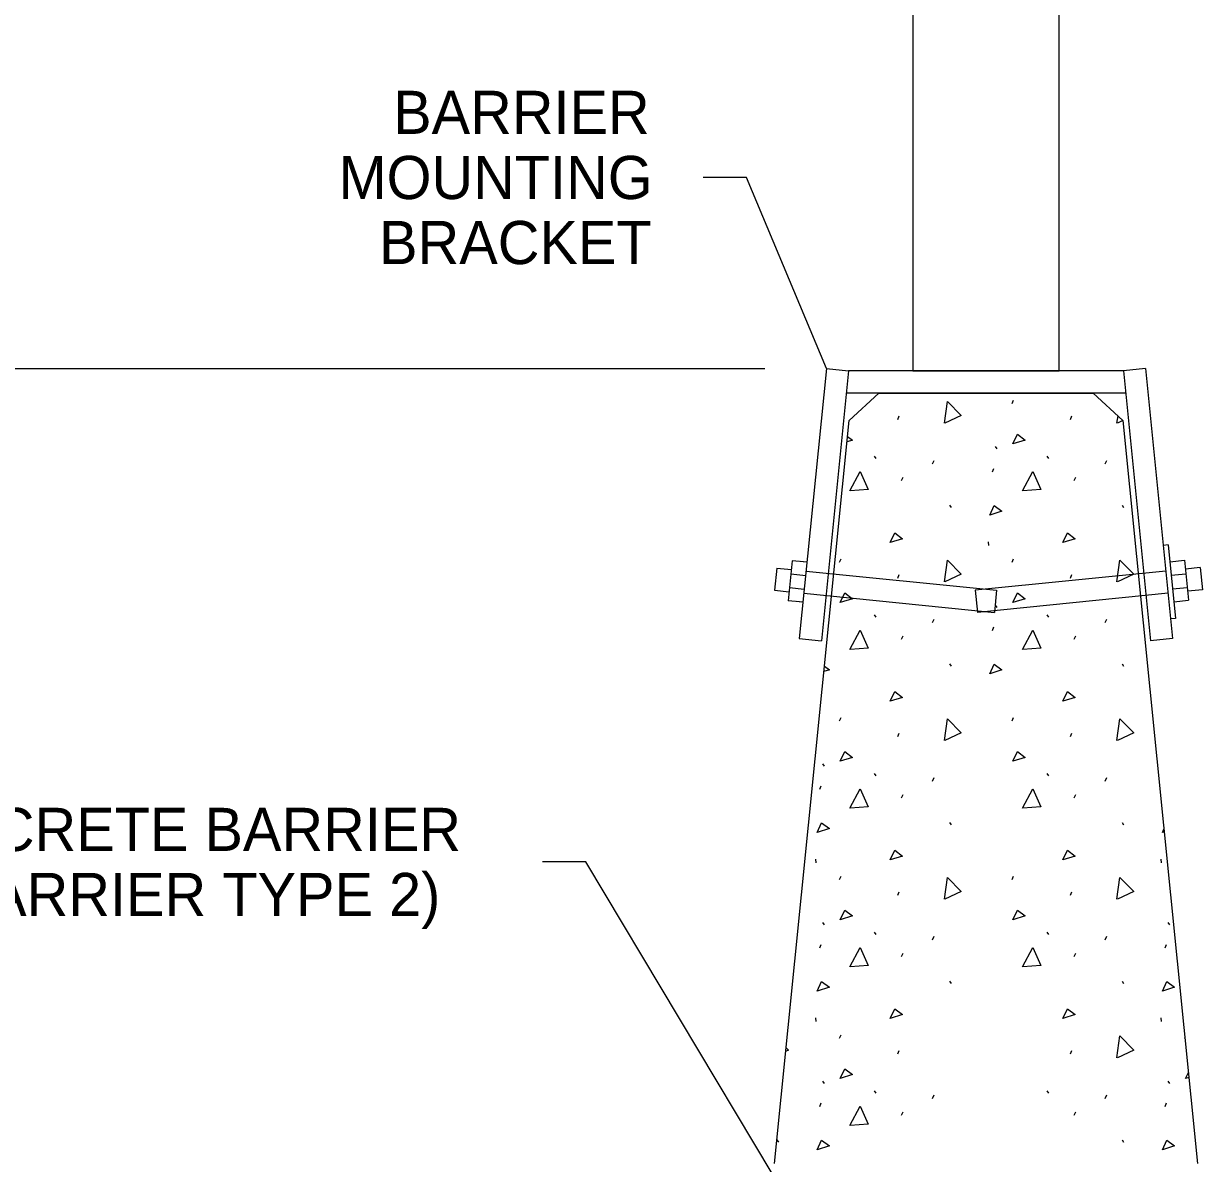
# Model space of a CAD drawing. Extents: x 99988 to 100172, y 99995 to 100047.
# Drawn here: x 100000.814 to 100002.726, y 100003.536 to 100005.385 of the extents above; entities that cross this region are included whole.
import ezdxf

# ---------------------------------------------------------------- set-up
doc = ezdxf.new("R2010")
doc.units = 0
for name, color, linetype in [('Level 1', 7, 'Continuous'), ('Level 15', 7, 'Continuous'), ('Level 20', 7, 'Continuous')]:
    doc.layers.add(name, color=color, linetype=linetype)

msp = doc.modelspace()

# ---------------------------------------------------------------- linework, layer by layer
at = {"layer": 'Level 1'}
for p, q in [((100002.2568, 100006.8162), (100002.2568, 100004.8216)), ((100002.4942, 100004.8216), (100002.4942, 100006.813)), ((100002.1168, 100004.8252), (100002.0727, 100004.3874)), ((100002.1526, 100004.8216), (100002.1085, 100004.3838)), ((100002.1168, 100004.8252), (100002.1526, 100004.8216)), ((100002.5983, 100004.8216), (100002.1526, 100004.8216)), ((100002.2568, 100004.8216), (100002.4942, 100004.8216)), ((100002.6341, 100004.8252), (100002.5983, 100004.8216)), ((100002.5983, 100004.8216), (100002.6424, 100004.3838)), ((100002.6341, 100004.8252), (100002.6782, 100004.3874)), ((100002.6019, 100004.7856), (100002.149, 100004.7856)), ((100002.1535, 100004.7413), (100002.2014, 100004.7856)), ((100002.2014, 100004.7856), (100002.5495, 100004.7856)), ((100002.4178, 100004.7685), (100002.4203, 100004.7741)), ((100002.5495, 100004.7856), (100002.5973, 100004.7413)), ((100002.0323, 100003.5365), (100002.1535, 100004.7413)), ((100002.2323, 100004.743), (100002.2348, 100004.7486)), ((100002.5123, 100004.743), (100002.5148, 100004.7486)), ((100002.5973, 100004.7413), (100002.7186, 100003.5362)), ((100002.3905, 100004.6989), (100002.393, 100004.6952)), ((100002.1943, 100004.6831), (100002.1967, 100004.6793)), ((100002.2888, 100004.6709), (100002.2913, 100004.6765)), ((100002.4743, 100004.6831), (100002.4767, 100004.6793)), ((100002.5688, 100004.6709), (100002.5713, 100004.6765)), ((100002.3858, 100004.6579), (100002.3883, 100004.6635)), ((100002.2385, 100004.6436), (100002.241, 100004.6492)), ((100002.5185, 100004.6436), (100002.521, 100004.6492)), ((100002.3162, 100004.6038), (100002.3187, 100004.6001)), ((100002.5962, 100004.6038), (100002.5987, 100004.6001)), ((100002.379, 100004.5442), (100002.3797, 100004.5386)), ((100002.6709, 100004.5394), (100002.663, 100004.5386)), ((100002.6709, 100004.5394), (100002.6829, 100004.4201)), ((100002.0613, 100004.5138), (100002.0548, 100004.4489)), ((100002.0852, 100004.5113), (100002.0613, 100004.5137)), ((100002.0788, 100004.512), (100002.0749, 100004.5124)), ((100002.1378, 100004.5112), (100002.1403, 100004.5168)), ((100002.4178, 100004.5112), (100002.4203, 100004.5168)), ((100002.6737, 100004.5121), (100002.6975, 100004.5146)), ((100002.6975, 100004.5146), (100002.7041, 100004.4498)), ((100002.083, 100004.4892), (100002.0591, 100004.4917)), ((100002.2323, 100004.4857), (100002.2348, 100004.4913)), ((100002.5123, 100004.4857), (100002.5148, 100004.4913)), ((100002.6759, 100004.4901), (100002.6998, 100004.4925)), ((100002.0807, 100004.4672), (100002.0569, 100004.4697)), ((100002.6781, 100004.4681), (100002.702, 100004.4705)), ((100002.0787, 100004.4465), (100002.0548, 100004.4489)), ((100002.6802, 100004.4473), (100002.7041, 100004.4497)), ((100002.1943, 100004.4258), (100002.1967, 100004.4221)), ((100002.3905, 100004.4416), (100002.393, 100004.4379)), ((100002.4743, 100004.4258), (100002.4767, 100004.4221)), ((100002.2888, 100004.4136), (100002.2913, 100004.4192)), ((100002.5688, 100004.4136), (100002.5713, 100004.4192)), ((100002.6829, 100004.4201), (100002.675, 100004.4193)), ((100002.2385, 100004.3864), (100002.241, 100004.392)), ((100002.3858, 100004.4007), (100002.3883, 100004.4063)), ((100002.5185, 100004.3864), (100002.521, 100004.392)), ((100002.0727, 100004.3874), (100002.1085, 100004.3838)), ((100002.6782, 100004.3874), (100002.6424, 100004.3838)), ((100002.3162, 100004.3466), (100002.3187, 100004.3429)), ((100002.5962, 100004.3466), (100002.5987, 100004.3429)), ((100002.1378, 100004.254), (100002.1403, 100004.2596)), ((100002.4178, 100004.254), (100002.4203, 100004.2596)), ((100002.2323, 100004.2285), (100002.2348, 100004.2341)), ((100002.5123, 100004.2285), (100002.5148, 100004.2341)), ((100002.1105, 100004.1844), (100002.113, 100004.1806)), ((100002.1943, 100004.1685), (100002.1967, 100004.1648)), ((100002.2888, 100004.1564), (100002.2913, 100004.162)), ((100002.4743, 100004.1685), (100002.4767, 100004.1648)), ((100002.5688, 100004.1564), (100002.5713, 100004.162)), ((100002.1058, 100004.1434), (100002.1083, 100004.149)), ((100002.2385, 100004.1291), (100002.241, 100004.1347)), ((100002.5185, 100004.1291), (100002.521, 100004.1347)), ((100002.3162, 100004.0893), (100002.3187, 100004.0856)), ((100002.5962, 100004.0893), (100002.5987, 100004.0856)), ((100002.099, 100004.0297), (100002.0997, 100004.0241)), ((100002.659, 100004.0297), (100002.6597, 100004.0241)), ((100002.1378, 100003.9967), (100002.1403, 100004.0023)), ((100002.4178, 100003.9967), (100002.4203, 100004.0023)), ((100002.2323, 100003.9712), (100002.2348, 100003.9768)), ((100002.5123, 100003.9712), (100002.5148, 100003.9768)), ((100002.1105, 100003.9271), (100002.113, 100003.9234)), ((100002.1943, 100003.9113), (100002.1967, 100003.9076)), ((100002.4743, 100003.9113), (100002.4767, 100003.9076)), ((100002.6705, 100003.9271), (100002.673, 100003.9234)), ((100002.1058, 100003.8861), (100002.1083, 100003.8917)), ((100002.2888, 100003.8991), (100002.2913, 100003.9047)), ((100002.5688, 100003.8991), (100002.5713, 100003.9047)), ((100002.6658, 100003.8861), (100002.6683, 100003.8917)), ((100002.2385, 100003.8718), (100002.241, 100003.8774)), ((100002.5185, 100003.8718), (100002.521, 100003.8774)), ((100002.3162, 100003.8321), (100002.3187, 100003.8283)), ((100002.5962, 100003.8321), (100002.5987, 100003.8283)), ((100002.099, 100003.7724), (100002.0997, 100003.7668)), ((100002.659, 100003.7724), (100002.6597, 100003.7668)), ((100002.1378, 100003.7394), (100002.1403, 100003.745)), ((100002.6978, 100003.7394), (100002.6981, 100003.7401)), ((100002.2323, 100003.714), (100002.2348, 100003.7196)), ((100002.5123, 100003.714), (100002.5148, 100003.7196)), ((100002.1105, 100003.6698), (100002.113, 100003.6661)), ((100002.6705, 100003.6698), (100002.673, 100003.6661)), ((100002.1943, 100003.654), (100002.1967, 100003.6503)), ((100002.2888, 100003.6419), (100002.2913, 100003.6475)), ((100002.4743, 100003.654), (100002.4767, 100003.6503)), ((100002.5688, 100003.6419), (100002.5713, 100003.6475)), ((100002.1058, 100003.6289), (100002.1083, 100003.6345)), ((100002.6658, 100003.6289), (100002.6683, 100003.6345)), ((100002.2385, 100003.6146), (100002.241, 100003.6202)), ((100002.5185, 100003.6146), (100002.521, 100003.6202)), ((100002.0362, 100003.5748), (100002.0387, 100003.5711)), ((100002.5962, 100003.5748), (100002.5987, 100003.5711))]:
    msp.add_line(p, q, dxfattribs=at)
for points in [[(100002.3079, 100004.7366), (100002.3128, 100004.7721), (100002.3351, 100004.7491), (100002.3085, 100004.7368)], [(100002.5879, 100004.7366), (100002.5896, 100004.7485)], [(100002.5974, 100004.7409), (100002.5885, 100004.7368)], [(100002.1509, 100004.7154), (100002.1589, 100004.7094), (100002.1501, 100004.7067)], [(100002.419, 100004.7032), (100002.4265, 100004.7188), (100002.4389, 100004.7094), (100002.419, 100004.7032)], [(100002.1546, 100004.6269), (100002.1714, 100004.6585), (100002.1844, 100004.6293), (100002.1552, 100004.6269)], [(100002.4346, 100004.6269), (100002.4514, 100004.6585), (100002.4644, 100004.6293), (100002.4352, 100004.6269)], [(100002.3815, 100004.5877), (100002.3889, 100004.6032), (100002.4014, 100004.5939), (100002.3815, 100004.5877)], [(100002.22, 100004.5432), (100002.2274, 100004.5588), (100002.2399, 100004.5495), (100002.22, 100004.5432)], [(100002.5, 100004.5432), (100002.5074, 100004.5588), (100002.5199, 100004.5495), (100002.5, 100004.5432)], [(100002.3079, 100004.4793), (100002.3128, 100004.5148), (100002.3351, 100004.4918), (100002.3085, 100004.4795)], [(100002.5879, 100004.4793), (100002.5928, 100004.5148), (100002.6151, 100004.4918), (100002.5885, 100004.4795)], [(100002.139, 100004.446), (100002.1465, 100004.4615), (100002.1589, 100004.4522), (100002.139, 100004.446)], [(100002.419, 100004.446), (100002.4265, 100004.4615), (100002.4389, 100004.4522), (100002.419, 100004.446)], [(100002.1546, 100004.3696), (100002.1714, 100004.4013), (100002.1844, 100004.3721), (100002.1552, 100004.3696)], [(100002.4346, 100004.3696), (100002.4514, 100004.4013), (100002.4644, 100004.3721), (100002.4352, 100004.3696)], [(100002.1134, 100004.3426), (100002.1214, 100004.3366), (100002.1125, 100004.3339)], [(100002.3815, 100004.3304), (100002.3889, 100004.346), (100002.4014, 100004.3366), (100002.3815, 100004.3304)], [(100002.22, 100004.286), (100002.2274, 100004.3015), (100002.2399, 100004.2922), (100002.22, 100004.286)], [(100002.5, 100004.286), (100002.5074, 100004.3015), (100002.5199, 100004.2922), (100002.5, 100004.286)], [(100002.3079, 100004.2221), (100002.3128, 100004.2576), (100002.3351, 100004.2346), (100002.3085, 100004.2223)], [(100002.5879, 100004.2221), (100002.5928, 100004.2576), (100002.6151, 100004.2346), (100002.5885, 100004.2223)], [(100002.139, 100004.1887), (100002.1465, 100004.2042), (100002.1589, 100004.1949), (100002.139, 100004.1887)], [(100002.419, 100004.1887), (100002.4265, 100004.2042), (100002.4389, 100004.1949), (100002.419, 100004.1887)], [(100002.1546, 100004.1123), (100002.1714, 100004.144), (100002.1844, 100004.1148), (100002.1552, 100004.1123)], [(100002.4346, 100004.1123), (100002.4514, 100004.144), (100002.4644, 100004.1148), (100002.4352, 100004.1123)], [(100002.1015, 100004.0732), (100002.1089, 100004.0887), (100002.1214, 100004.0794), (100002.1015, 100004.0732)], [(100002.6615, 100004.0732), (100002.664, 100004.0785)], [(100002.6645, 100004.0741), (100002.6615, 100004.0732)], [(100002.22, 100004.0287), (100002.2274, 100004.0443), (100002.2399, 100004.0349), (100002.22, 100004.0287)], [(100002.5, 100004.0287), (100002.5074, 100004.0443), (100002.5199, 100004.0349), (100002.5, 100004.0287)], [(100002.3079, 100003.9648), (100002.3128, 100004.0003), (100002.3351, 100003.9773), (100002.3085, 100003.965)], [(100002.5879, 100003.9648), (100002.5928, 100004.0003), (100002.6151, 100003.9773), (100002.5885, 100003.965)], [(100002.139, 100003.9314), (100002.1465, 100003.947), (100002.1589, 100003.9377), (100002.139, 100003.9314)], [(100002.419, 100003.9314), (100002.4265, 100003.947), (100002.4389, 100003.9377), (100002.419, 100003.9314)], [(100002.1546, 100003.8551), (100002.1714, 100003.8868), (100002.1844, 100003.8576), (100002.1552, 100003.8551)], [(100002.4346, 100003.8551), (100002.4514, 100003.8868), (100002.4644, 100003.8576), (100002.4352, 100003.8551)], [(100002.1015, 100003.8159), (100002.1089, 100003.8314), (100002.1214, 100003.8221), (100002.1015, 100003.8159)], [(100002.6615, 100003.8159), (100002.6689, 100003.8314), (100002.6814, 100003.8221), (100002.6615, 100003.8159)], [(100002.22, 100003.7715), (100002.2274, 100003.787), (100002.2399, 100003.7777), (100002.22, 100003.7715)], [(100002.5, 100003.7715), (100002.5074, 100003.787), (100002.5199, 100003.7777), (100002.5, 100003.7715)], [(100002.5879, 100003.7075), (100002.5928, 100003.7431), (100002.6151, 100003.7201), (100002.5885, 100003.7077)], [(100002.0512, 100003.7241), (100002.0551, 100003.7201), (100002.0505, 100003.718)], [(100002.139, 100003.6742), (100002.1465, 100003.6897), (100002.1589, 100003.6804), (100002.139, 100003.6742)], [(100002.699, 100003.6742), (100002.7037, 100003.684)], [(100002.7045, 100003.6759), (100002.699, 100003.6742)], [(100002.1546, 100003.5978), (100002.1714, 100003.6295), (100002.1844, 100003.6003), (100002.1552, 100003.5978)], [(100002.1015, 100003.5586), (100002.1089, 100003.5742), (100002.1214, 100003.5649), (100002.1015, 100003.5586)], [(100002.6615, 100003.5586), (100002.6689, 100003.5742), (100002.6814, 100003.5649), (100002.6615, 100003.5586)]]:
    msp.add_lwpolyline(points, dxfattribs=at)
at = {"layer": 'Level 15'}
for p, q in [((100000.4266, 100004.8252), (100002.0168, 100004.8252)), ((100002.7229, 100004.5025), (100002.699, 100004.5001)), ((100002.7229, 100004.5025), (100002.7265, 100004.4667)), ((100002.036, 100004.5017), (100002.0324, 100004.4658)), ((100002.036, 100004.5017), (100002.0598, 100004.4993)), ((100002.0837, 100004.4969), (100002.3927, 100004.4658)), ((100002.6672, 100004.4969), (100002.3581, 100004.4658)), ((100002.0324, 100004.4658), (100002.0562, 100004.4634)), ((100002.3581, 100004.4658), (100002.3617, 100004.4299)), ((100002.3927, 100004.4658), (100002.3891, 100004.4299)), ((100002.7265, 100004.4667), (100002.7026, 100004.4643)), ((100002.0762, 100004.4468), (100002.0685, 100004.4475)), ((100002.0801, 100004.461), (100002.3891, 100004.4299)), ((100002.6708, 100004.461), (100002.3617, 100004.4299))]:
    msp.add_line(p, q, dxfattribs=at)
for points in [[(100002.1168, 100004.8252), (100001.9868, 100005.1352), (100001.9168, 100005.1352)], [(100002.0302, 100003.5173), (100001.7263, 100004.0253), (100001.6563, 100004.0253)]]:
    msp.add_lwpolyline(points, dxfattribs=at)

# ---------------------------------------------------------------- texts
at = {"layer": 'Level 20'}
for s, p in [('BARRIER', (100001.4139, 100005.2058)), ('MOUNTING', (100001.3253, 100005.1002)), ('BRACKET', (100001.3911, 100004.9947)), ('CONCRETE BARRIER', (100000.5566, 100004.0431)), ('(CONC. BARRIER TYPE 2)', (100000.3358, 100003.9375))]:
    msp.add_text(s, height=0.07, dxfattribs=at).set_placement(p)

doc.saveas('drawing.dxf')
